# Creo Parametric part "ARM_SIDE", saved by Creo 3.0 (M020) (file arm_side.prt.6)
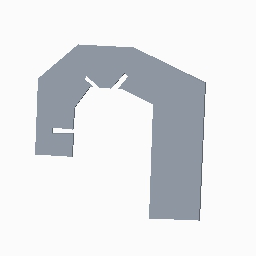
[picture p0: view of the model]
Units: millimeter Newton Second (mmNs); MM, TONNE, SECS

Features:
  1. datum plane "RIGHT"
  2. datum plane "TOP"
  3. datum plane "FRONT"
  4. coordinate system
  5. sketch "Sketch 1"
  6. extrusion "Extrude 1"
  7. sketch "Sketch 2"
  8. sketch "Sketch 3"
  9. extruded cut "Extrude 3"
  10. sketch "Sketch 4"
  11. extruded cut "Extrude 4"
  12. sketch "Sketch 5"
  13. extruded cut "Extrude 5"

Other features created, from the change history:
  datum plane "DTM1"
  sketch "Sketch 2"
  extruded cut "Extrude 2"
  extruded cut "Extrude 3"

Surfaces: 27 plane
